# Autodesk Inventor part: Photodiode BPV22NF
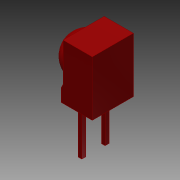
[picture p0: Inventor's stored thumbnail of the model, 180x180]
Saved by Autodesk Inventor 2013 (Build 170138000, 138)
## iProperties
Created: 2012-08
Part Number: Photodiode BPV22NF
Material: PC/ABS-Kunststoff
Document SubType Name: Modeling
Designer: rYan
Mass: 0.15883 g
Surface Area: 1.49802 cm^2
Volume: 0.106383 cm^3
Density: 1.493 g/cm^3
Author: rYan
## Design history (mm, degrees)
sketch "Skizze1"
  geometry: L1 (0, 0)-(0, 6); L2 (0, 6)-(3.2, 6); L3 (3.2, 6)-(3.2, 1.8); L4 (3.2, 1.8)-(3.4, 1.4); L5 (3.4, 1.4)-(3.4, 0); L6 (3.4, 0)-(0, 0)
  constraints: 12 end point, 2 parallel, 2 perpendicular, 1 vertical
  dimensions: "d0" = 3.4 distance of L5.end L1.start; "d1" = 6 distance of L1.start L1.end; "d2" = 3.2 distance of L1.end L2.end; "d5" = 4.2 distance of L2.end L3.end; "d6" = 1.4 distance of L4.end L5.end
extrude "Extrusion1" new body sketch "Skizze1" stored distance "d7" = 4.5; taper "d8" = 0 deg
sketch "Skizze3"
  geometry: L1 (0, 6)-(3.2, 6) reference; L2 (0, 0)-(0, 6) reference; L3 (3.2, 6)-(3.2, 1.8) reference; L4 (5, 5.856)-(5, 1.8); L5 (2.75, 1.35)-(2.75, 5.85); A1 r 2.25 centre (2.75, 3.6) between (2.75, 1.35) and (2.75, 5.85)
  constraints: 4 end point, 2 parallel, 2 point on circle, 1 centre point, 1 midpoint, 1 tangent
  dimensions: "d12" = 4.5 diameter of A1; "d13" = 5 distance between parallel lines of L4 L2; "d14" = 2.4 distance from line of L1 A1.centre
revolve "Umdrehung1" sketch "Skizze3" stored, may be unused: angle "d15" = 90 deg
sketch "Skizze4"
  geometry: L1 (1.9, -0.755)-(2.3, -0.755); L2 (2.3, -0.755)-(2.3, -1.205); L3 (2.3, -1.205)-(1.9, -1.205); L4 (1.9, -1.205)-(1.9, -0.755); L5 (1.9, -3.295)-(2.3, -3.295); L6 (2.3, -3.295)-(2.3, -3.745); L7 (2.3, -3.745)-(1.9, -3.745); L8 (1.9, -3.745)-(1.9, -3.295); L9 (3.4, 0)-(3.4, -4.5) reference; L10 (0, 0)-(3.4, 0) reference; L11 (0, -4.5)-(0, 0) reference; L12 (3.4, -4.5)-(0, -4.5) reference; L13 (0, -2.25)-(3.4, -2.25)
  constraints: 18 end point, 4 parallel, 2 horizontal, 2 perpendicular, 1 midpoint, 4 other
  dimensions: "d16" = 0.4 distance of L1.start L1.end; "d18" = 0.45 distance of L3.end L1.start; "d19" = 2.09 distance between parallel lines of L3 L5; "d20" = 1.1 distance between parallel lines of L2 L9
extrude "Extrusion2" join sketch "Skizze4" distance "d21" = 5; taper "d22" = 0 deg
node "Volumenkörper1"
node "Projizierte Kontur1"
